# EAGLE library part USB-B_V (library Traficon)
USB Vertical connector
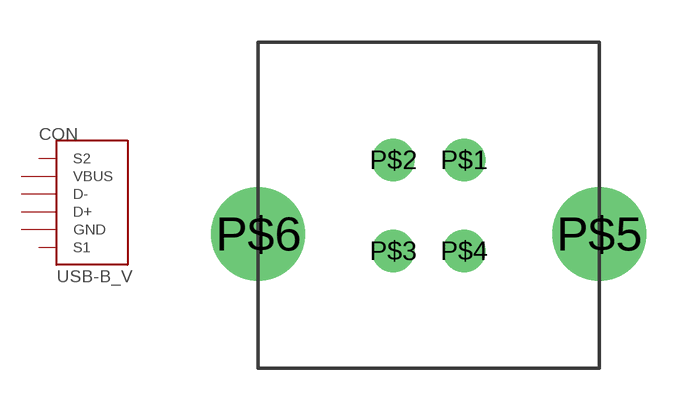
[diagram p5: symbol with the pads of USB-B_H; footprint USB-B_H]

Designator prefix CON

## USB-B_V  [USB-B_H]
P$1  VBUS  pas
P$2  D-  pas
P$3  D+  pas
P$4  GND  pas
P$5  S1  pas
P$6  S2  pas

## Footprint USB-B_H (pad centres in mm)
drill 1 round: P$1 1.25,1.6; P$2 -1.25,1.6; P$3 -1.25,-1.61; P$4 1.25,-1.61
drill 2.3 round: P$5 6.02,-1.01; P$6 -6.02,-1.01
